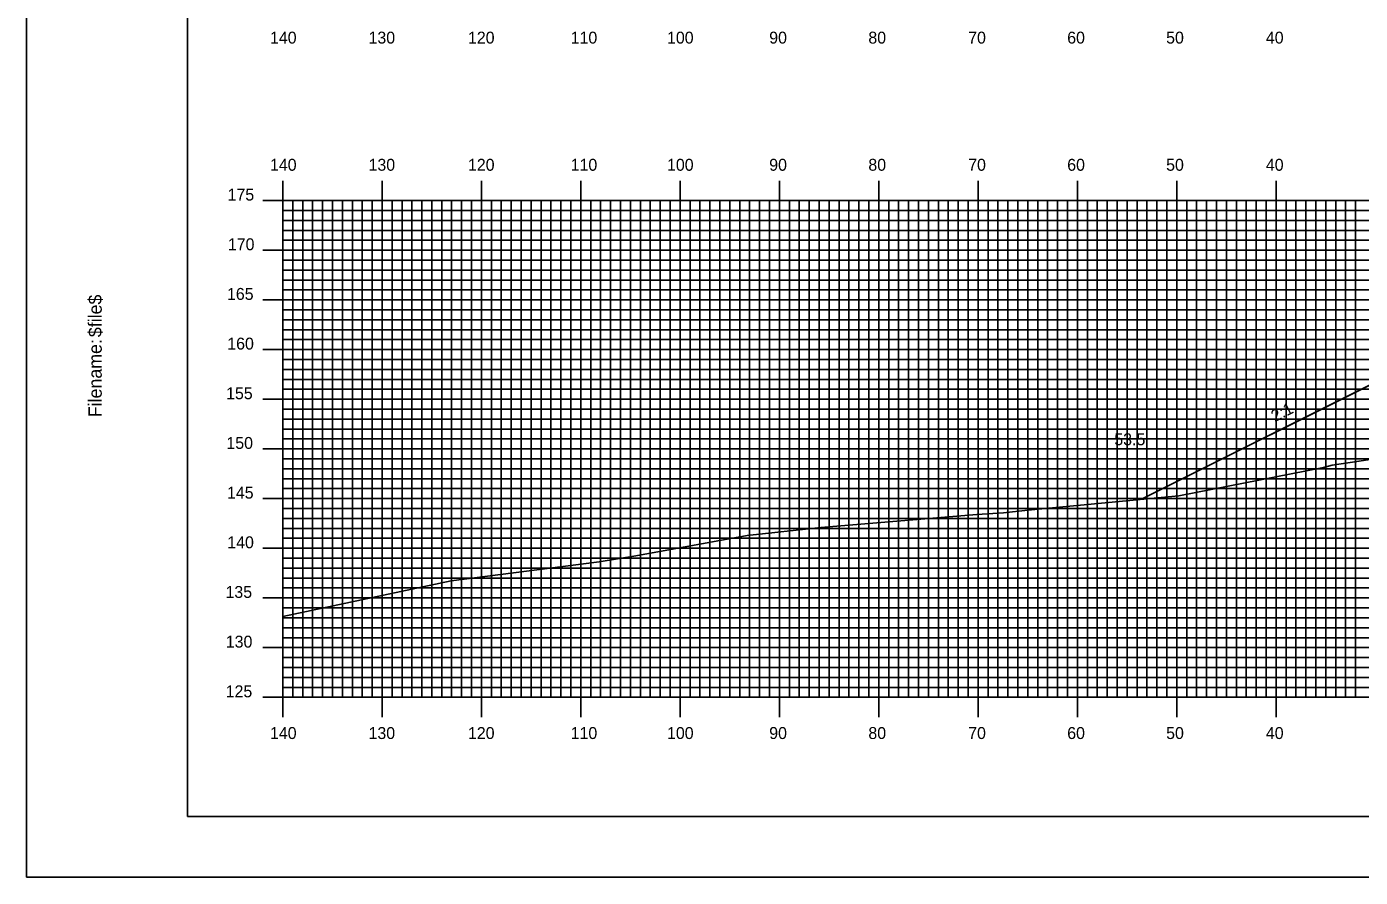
# Model space of a CAD drawing. Extents: x 1793272 to 1793615, y 442591 to 442811.
# Drawn here: x 1793272 to 1793406.3, y 442590.5 to 442676.2 of the extents above; entities that cross this region are included whole.
import ezdxf

# ---------------------------------------------------------------- set-up
doc = ezdxf.new("R2010")
doc.units = 0
for name, color, linetype in [('ANNOTATION', 7, 'Continuous'), ('BORDER', 7, 'Continuous'), ('D_Roadway_Centerline', 7, 'Continuous'), ('D_Roadway_SlopeLines', 7, 'Continuous'), ('D_Text_Standard', 7, 'Continuous'), ('H_V ANNOTATION', 7, 'Continuous'), ('MAJOR', 7, 'Continuous'), ('MINOR', 7, 'Continuous'), ('PLOT BOUNDARY', 7, 'Continuous'), ('S_Roadway_Centerline', 7, 'Continuous')]:
    doc.layers.add(name, color=color, linetype=linetype)

msp = doc.modelspace()

# ---------------------------------------------------------------- linework, layer by layer
at = {"layer": 'BORDER'}
msp.add_lwpolyline([(1793288.2, 442596.67), (1793608.2, 442596.67), (1793608.2, 442806.67), (1793288.2, 442806.67)], close=True, dxfattribs=at)
at = {"layer": 'D_Roadway_Centerline'}
msp.add_lwpolyline([(1793384.25, 442628.61), (1793410.05, 442641.51), (1793414.8, 442643.88), (1793417.8, 442644), (1793425.8, 442644.32), (1793437.8, 442644.08), (1793449.8, 442643.84), (1793457.8, 442643.52), (1793467.97, 442640.98), (1793471.97, 442639.98)], dxfattribs=at)
at = {"layer": 'D_Roadway_SlopeLines'}
msp.add_lwpolyline([(1793414.8, 442643.88), (1793384.25, 442628.61)], dxfattribs=at)
at = {"layer": 'MAJOR'}
for p, q in [((1793297.8, 442660.67), (1793297.8, 442658.67)), ((1793307.8, 442660.67), (1793307.8, 442658.67)), ((1793317.8, 442660.67), (1793317.8, 442658.67)), ((1793327.8, 442660.67), (1793327.8, 442658.67)), ((1793337.8, 442660.67), (1793337.8, 442658.67)), ((1793347.8, 442660.67), (1793347.8, 442658.67)), ((1793357.8, 442660.67), (1793357.8, 442658.67)), ((1793367.8, 442660.67), (1793367.8, 442658.67)), ((1793377.8, 442660.67), (1793377.8, 442658.67)), ((1793387.8, 442660.67), (1793387.8, 442658.67)), ((1793397.8, 442660.67), (1793397.8, 442658.67)), ((1793295.8, 442658.67), (1793297.8, 442658.67)), ((1793297.8, 442658.67), (1793577.8, 442658.67)), ((1793297.8, 442608.67), (1793297.8, 442658.67)), ((1793297.8, 442608.67), (1793297.8, 442658.67)), ((1793297.8, 442658.67), (1793577.8, 442658.67)), ((1793307.8, 442608.67), (1793307.8, 442658.67)), ((1793317.8, 442608.67), (1793317.8, 442658.67)), ((1793327.8, 442608.67), (1793327.8, 442658.67)), ((1793337.8, 442608.67), (1793337.8, 442658.67)), ((1793347.8, 442608.67), (1793347.8, 442658.67)), ((1793357.8, 442608.67), (1793357.8, 442658.67)), ((1793367.8, 442608.67), (1793367.8, 442658.67)), ((1793377.8, 442608.67), (1793377.8, 442658.67)), ((1793387.8, 442608.67), (1793387.8, 442658.67)), ((1793397.8, 442608.67), (1793397.8, 442658.67)), ((1793295.8, 442653.67), (1793297.8, 442653.67)), ((1793297.8, 442653.67), (1793577.8, 442653.67)), ((1793295.8, 442648.67), (1793297.8, 442648.67)), ((1793297.8, 442648.67), (1793577.8, 442648.67)), ((1793295.8, 442643.67), (1793297.8, 442643.67)), ((1793297.8, 442643.67), (1793577.8, 442643.67)), ((1793295.8, 442638.67), (1793297.8, 442638.67)), ((1793297.8, 442638.67), (1793577.8, 442638.67)), ((1793295.8, 442633.67), (1793297.8, 442633.67)), ((1793297.8, 442633.67), (1793577.8, 442633.67)), ((1793295.8, 442628.67), (1793297.8, 442628.67)), ((1793297.8, 442628.67), (1793577.8, 442628.67)), ((1793295.8, 442623.67), (1793297.8, 442623.67)), ((1793297.8, 442623.67), (1793577.8, 442623.67)), ((1793295.8, 442618.67), (1793297.8, 442618.67)), ((1793297.8, 442618.67), (1793577.8, 442618.67)), ((1793295.8, 442613.67), (1793297.8, 442613.67)), ((1793297.8, 442613.67), (1793577.8, 442613.67)), ((1793295.8, 442608.67), (1793297.8, 442608.67)), ((1793297.8, 442608.67), (1793577.8, 442608.67)), ((1793297.8, 442608.67), (1793577.8, 442608.67)), ((1793297.8, 442606.66), (1793297.8, 442608.67)), ((1793307.8, 442606.66), (1793307.8, 442608.67)), ((1793317.8, 442606.66), (1793317.8, 442608.67)), ((1793327.8, 442606.66), (1793327.8, 442608.67)), ((1793337.8, 442606.66), (1793337.8, 442608.67)), ((1793347.8, 442606.66), (1793347.8, 442608.67)), ((1793357.8, 442606.66), (1793357.8, 442608.67)), ((1793367.8, 442606.66), (1793367.8, 442608.67)), ((1793377.8, 442606.66), (1793377.8, 442608.67)), ((1793387.8, 442606.66), (1793387.8, 442608.67)), ((1793397.8, 442606.66), (1793397.8, 442608.67))]:
    msp.add_line(p, q, dxfattribs=at)
at = {"layer": 'MINOR'}
for p, q in [((1793298.8, 442608.67), (1793298.8, 442658.67)), ((1793299.8, 442608.67), (1793299.8, 442658.67)), ((1793300.8, 442608.67), (1793300.8, 442658.67)), ((1793301.8, 442608.67), (1793301.8, 442658.67)), ((1793302.8, 442608.67), (1793302.8, 442658.67)), ((1793303.8, 442608.67), (1793303.8, 442658.67)), ((1793304.8, 442608.67), (1793304.8, 442658.67)), ((1793305.8, 442608.67), (1793305.8, 442658.67)), ((1793306.8, 442608.67), (1793306.8, 442658.67)), ((1793308.8, 442608.67), (1793308.8, 442658.67)), ((1793309.8, 442608.67), (1793309.8, 442658.67)), ((1793310.8, 442608.67), (1793310.8, 442658.67)), ((1793311.8, 442608.67), (1793311.8, 442658.67)), ((1793312.8, 442608.67), (1793312.8, 442658.67)), ((1793313.8, 442608.67), (1793313.8, 442658.67)), ((1793314.8, 442608.67), (1793314.8, 442658.67)), ((1793315.8, 442608.67), (1793315.8, 442658.67)), ((1793316.8, 442608.67), (1793316.8, 442658.67)), ((1793318.8, 442608.67), (1793318.8, 442658.67)), ((1793319.8, 442608.67), (1793319.8, 442658.67)), ((1793320.8, 442608.67), (1793320.8, 442658.67)), ((1793321.8, 442608.67), (1793321.8, 442658.67)), ((1793322.8, 442608.67), (1793322.8, 442658.67)), ((1793323.8, 442608.67), (1793323.8, 442658.67)), ((1793324.8, 442608.67), (1793324.8, 442658.67)), ((1793325.8, 442608.67), (1793325.8, 442658.67)), ((1793326.8, 442608.67), (1793326.8, 442658.67)), ((1793328.8, 442608.67), (1793328.8, 442658.67)), ((1793329.8, 442608.67), (1793329.8, 442658.67)), ((1793330.8, 442608.67), (1793330.8, 442658.67)), ((1793331.8, 442608.67), (1793331.8, 442658.67)), ((1793332.8, 442608.67), (1793332.8, 442658.67)), ((1793333.8, 442608.67), (1793333.8, 442658.67)), ((1793334.8, 442608.67), (1793334.8, 442658.67)), ((1793335.8, 442608.67), (1793335.8, 442658.67)), ((1793336.8, 442608.67), (1793336.8, 442658.67)), ((1793338.8, 442608.67), (1793338.8, 442658.67)), ((1793339.8, 442608.67), (1793339.8, 442658.67)), ((1793340.8, 442608.67), (1793340.8, 442658.67)), ((1793341.8, 442608.67), (1793341.8, 442658.67)), ((1793342.8, 442608.67), (1793342.8, 442658.67)), ((1793343.8, 442608.67), (1793343.8, 442658.67)), ((1793344.8, 442608.67), (1793344.8, 442658.67)), ((1793345.8, 442608.67), (1793345.8, 442658.67)), ((1793346.8, 442608.67), (1793346.8, 442658.67)), ((1793348.8, 442608.67), (1793348.8, 442658.67)), ((1793349.8, 442608.67), (1793349.8, 442658.67)), ((1793350.8, 442608.67), (1793350.8, 442658.67)), ((1793351.8, 442608.67), (1793351.8, 442658.67)), ((1793352.8, 442608.67), (1793352.8, 442658.67)), ((1793353.8, 442608.67), (1793353.8, 442658.67)), ((1793354.8, 442608.67), (1793354.8, 442658.67)), ((1793355.8, 442608.67), (1793355.8, 442658.67)), ((1793356.8, 442608.67), (1793356.8, 442658.67)), ((1793358.8, 442608.67), (1793358.8, 442658.67)), ((1793359.8, 442608.67), (1793359.8, 442658.67)), ((1793360.8, 442608.67), (1793360.8, 442658.67)), ((1793361.8, 442608.67), (1793361.8, 442658.67)), ((1793362.8, 442608.67), (1793362.8, 442658.67)), ((1793363.8, 442608.67), (1793363.8, 442658.67)), ((1793364.8, 442608.67), (1793364.8, 442658.67)), ((1793365.8, 442608.67), (1793365.8, 442658.67)), ((1793366.8, 442608.67), (1793366.8, 442658.67)), ((1793368.8, 442608.67), (1793368.8, 442658.67)), ((1793369.8, 442608.67), (1793369.8, 442658.67)), ((1793370.8, 442608.67), (1793370.8, 442658.67)), ((1793371.8, 442608.67), (1793371.8, 442658.67)), ((1793372.8, 442608.67), (1793372.8, 442658.67)), ((1793373.8, 442608.67), (1793373.8, 442658.67)), ((1793374.8, 442608.67), (1793374.8, 442658.67)), ((1793375.8, 442608.67), (1793375.8, 442658.67)), ((1793376.8, 442608.67), (1793376.8, 442658.67)), ((1793378.8, 442608.67), (1793378.8, 442658.67)), ((1793379.8, 442608.67), (1793379.8, 442658.67)), ((1793380.8, 442608.67), (1793380.8, 442658.67)), ((1793381.8, 442608.67), (1793381.8, 442658.67)), ((1793382.8, 442608.67), (1793382.8, 442658.67)), ((1793383.8, 442608.67), (1793383.8, 442658.67)), ((1793384.8, 442608.67), (1793384.8, 442658.67)), ((1793385.8, 442608.67), (1793385.8, 442658.67)), ((1793386.8, 442608.67), (1793386.8, 442658.67)), ((1793388.8, 442608.67), (1793388.8, 442658.67)), ((1793389.8, 442608.67), (1793389.8, 442658.67)), ((1793390.8, 442608.67), (1793390.8, 442658.67)), ((1793391.8, 442608.67), (1793391.8, 442658.67)), ((1793392.8, 442608.67), (1793392.8, 442658.67)), ((1793393.8, 442608.67), (1793393.8, 442658.67)), ((1793394.8, 442608.67), (1793394.8, 442658.67)), ((1793395.8, 442608.67), (1793395.8, 442658.67)), ((1793396.8, 442608.67), (1793396.8, 442658.67)), ((1793398.8, 442608.67), (1793398.8, 442658.67)), ((1793399.8, 442608.67), (1793399.8, 442658.67)), ((1793400.8, 442608.67), (1793400.8, 442658.67)), ((1793401.8, 442608.67), (1793401.8, 442658.67)), ((1793402.8, 442608.67), (1793402.8, 442658.67)), ((1793403.8, 442608.67), (1793403.8, 442658.67)), ((1793404.8, 442608.67), (1793404.8, 442658.67)), ((1793405.8, 442608.67), (1793405.8, 442658.67)), ((1793297.8, 442657.67), (1793577.8, 442657.67)), ((1793297.8, 442657.67), (1793299.8, 442657.67)), ((1793297.8, 442656.67), (1793577.8, 442656.67)), ((1793297.8, 442656.67), (1793299.8, 442656.67)), ((1793297.8, 442655.67), (1793577.8, 442655.67)), ((1793297.8, 442655.67), (1793299.8, 442655.67)), ((1793297.8, 442654.67), (1793577.8, 442654.67)), ((1793297.8, 442654.67), (1793299.8, 442654.67)), ((1793297.8, 442652.67), (1793577.8, 442652.67)), ((1793297.8, 442652.67), (1793299.8, 442652.67)), ((1793297.8, 442651.67), (1793577.8, 442651.67)), ((1793297.8, 442651.67), (1793299.8, 442651.67)), ((1793297.8, 442650.67), (1793577.8, 442650.67)), ((1793297.8, 442650.67), (1793299.8, 442650.67)), ((1793297.8, 442649.67), (1793577.8, 442649.67)), ((1793297.8, 442649.67), (1793299.8, 442649.67)), ((1793297.8, 442647.67), (1793577.8, 442647.67)), ((1793297.8, 442647.67), (1793299.8, 442647.67)), ((1793297.8, 442646.67), (1793577.8, 442646.67)), ((1793297.8, 442646.67), (1793299.8, 442646.67)), ((1793297.8, 442645.67), (1793577.8, 442645.67)), ((1793297.8, 442645.67), (1793299.8, 442645.67)), ((1793297.8, 442644.67), (1793577.8, 442644.67)), ((1793297.8, 442644.67), (1793299.8, 442644.67)), ((1793297.8, 442642.67), (1793577.8, 442642.67)), ((1793297.8, 442642.67), (1793299.8, 442642.67)), ((1793297.8, 442641.67), (1793577.8, 442641.67)), ((1793297.8, 442641.67), (1793299.8, 442641.67)), ((1793297.8, 442640.67), (1793577.8, 442640.67)), ((1793297.8, 442640.67), (1793299.8, 442640.67)), ((1793297.8, 442639.67), (1793577.8, 442639.67)), ((1793297.8, 442639.67), (1793299.8, 442639.67)), ((1793297.8, 442637.67), (1793577.8, 442637.67)), ((1793297.8, 442637.67), (1793299.8, 442637.67)), ((1793297.8, 442636.67), (1793577.8, 442636.67)), ((1793297.8, 442636.67), (1793299.8, 442636.67)), ((1793297.8, 442635.67), (1793577.8, 442635.67)), ((1793297.8, 442635.67), (1793299.8, 442635.67)), ((1793297.8, 442634.67), (1793577.8, 442634.67)), ((1793297.8, 442634.67), (1793299.8, 442634.67)), ((1793297.8, 442632.67), (1793577.8, 442632.67)), ((1793297.8, 442632.67), (1793299.8, 442632.67)), ((1793297.8, 442631.67), (1793577.8, 442631.67)), ((1793297.8, 442631.67), (1793299.8, 442631.67)), ((1793297.8, 442630.67), (1793577.8, 442630.67)), ((1793297.8, 442630.67), (1793299.8, 442630.67)), ((1793297.8, 442629.67), (1793577.8, 442629.67)), ((1793297.8, 442629.67), (1793299.8, 442629.67)), ((1793297.8, 442627.67), (1793577.8, 442627.67)), ((1793297.8, 442627.67), (1793299.8, 442627.67)), ((1793297.8, 442626.67), (1793577.8, 442626.67)), ((1793297.8, 442626.67), (1793299.8, 442626.67)), ((1793297.8, 442625.67), (1793577.8, 442625.67)), ((1793297.8, 442625.67), (1793299.8, 442625.67)), ((1793297.8, 442624.67), (1793577.8, 442624.67)), ((1793297.8, 442624.67), (1793299.8, 442624.67)), ((1793297.8, 442622.67), (1793577.8, 442622.67)), ((1793297.8, 442622.67), (1793299.8, 442622.67)), ((1793297.8, 442621.67), (1793577.8, 442621.67)), ((1793297.8, 442621.67), (1793299.8, 442621.67)), ((1793297.8, 442620.67), (1793577.8, 442620.67)), ((1793297.8, 442620.67), (1793299.8, 442620.67)), ((1793297.8, 442619.67), (1793577.8, 442619.67)), ((1793297.8, 442619.67), (1793299.8, 442619.67)), ((1793297.8, 442617.67), (1793577.8, 442617.67)), ((1793297.8, 442617.67), (1793299.8, 442617.67)), ((1793297.8, 442616.67), (1793577.8, 442616.67)), ((1793297.8, 442616.67), (1793299.8, 442616.67)), ((1793297.8, 442615.67), (1793577.8, 442615.67)), ((1793297.8, 442615.67), (1793299.8, 442615.67)), ((1793297.8, 442614.67), (1793577.8, 442614.67)), ((1793297.8, 442614.67), (1793299.8, 442614.67)), ((1793297.8, 442612.67), (1793577.8, 442612.67)), ((1793297.8, 442612.67), (1793299.8, 442612.67)), ((1793297.8, 442611.67), (1793577.8, 442611.67)), ((1793297.8, 442611.67), (1793299.8, 442611.67)), ((1793297.8, 442610.67), (1793577.8, 442610.67)), ((1793297.8, 442610.67), (1793299.8, 442610.67)), ((1793297.8, 442609.67), (1793577.8, 442609.67)), ((1793297.8, 442609.67), (1793299.8, 442609.67))]:
    msp.add_line(p, q, dxfattribs=at)
at = {"layer": 'PLOT BOUNDARY'}
msp.add_lwpolyline([(1793272.01, 442590.55), (1793612.01, 442590.55), (1793612.01, 442810.55), (1793272.01, 442810.55)], close=True, dxfattribs=at)
at = {"layer": 'S_Roadway_Centerline'}
msp.add_lwpolyline([(1793297.8, 442616.8), (1793314.74, 442620.39), (1793329.64, 442622.31), (1793333.34, 442622.91), (1793344.55, 442624.94), (1793351.98, 442625.77), (1793367.66, 442627.06), (1793370.37, 442627.24), (1793372.8, 442627.52), (1793388, 442628.96), (1793402.56, 442631.8), (1793403.43, 442632.02), (1793405.92, 442632.4), (1793406.12, 442632.43), (1793406.15, 442632.44), (1793406.17, 442632.44), (1793415.52, 442633.88)], dxfattribs=at)

# ---------------------------------------------------------------- texts
at = {"layer": 'ANNOTATION'}
msp.add_text('2:1', height=1.2, rotation=26.5651, dxfattribs=at).set_placement((1793397.67, 442636.35))
at = {"layer": 'BORDER'}
for s, p in [('$file$', (1793279.57, 442644.92)), ('Filename:', (1793279.57, 442636.86))]:
    msp.add_text(s, height=1.339, rotation=90, dxfattribs=at).set_placement(p)
at = {"layer": 'D_Text_Standard'}
msp.add_text("53.5'", height=1.2, dxfattribs=at).set_placement((1793381.51, 442634.04))
at = {"layer": 'H_V ANNOTATION'}
for s, p in [('140', (1793296.51, 442674.47)), ('130', (1793306.43, 442674.47)), ('120', (1793316.44, 442674.47)), ('110', (1793326.78, 442674.47)), ('100', (1793336.48, 442674.47)), ('90', (1793346.77, 442674.47)), ('80', (1793356.75, 442674.47)), ('70', (1793366.8, 442674.47)), ('60', (1793376.77, 442674.47)), ('50', (1793386.73, 442674.47)), ('40', (1793396.77, 442674.47)), ('140', (1793296.51, 442661.67)), ('130', (1793306.43, 442661.67)), ('120', (1793316.44, 442661.67)), ('110', (1793326.78, 442661.67)), ('100', (1793336.48, 442661.67)), ('90', (1793346.77, 442661.67)), ('80', (1793356.75, 442661.67)), ('70', (1793366.8, 442661.67)), ('60', (1793376.77, 442661.67)), ('50', (1793386.73, 442661.67)), ('40', (1793396.77, 442661.67)), ('175', (1793292.24, 442658.67)), ('170', (1793292.27, 442653.67)), ('165', (1793292.18, 442648.67)), ('160', (1793292.21, 442643.67)), ('155', (1793292.09, 442638.67)), ('150', (1793292.12, 442633.67)), ('145', (1793292.18, 442628.67)), ('140', (1793292.21, 442623.67)), ('135', (1793292.03, 442618.67)), ('130', (1793292.06, 442613.67)), ('125', (1793292.05, 442608.67)), ('140', (1793296.51, 442604.47)), ('130', (1793306.43, 442604.47)), ('120', (1793316.44, 442604.47)), ('110', (1793326.78, 442604.47)), ('100', (1793336.48, 442604.47)), ('90', (1793346.77, 442604.47)), ('80', (1793356.75, 442604.47)), ('70', (1793366.8, 442604.47)), ('60', (1793376.77, 442604.47)), ('50', (1793386.73, 442604.47)), ('40', (1793396.77, 442604.47))]:
    msp.add_text(s, height=1.2, dxfattribs=at).set_placement(p)
at = {"layer": 'MAJOR'}
msp.add_text('-', height=0.012, dxfattribs=at).set_placement((1793297.79, 442608.67))

doc.saveas('drawing.dxf')
